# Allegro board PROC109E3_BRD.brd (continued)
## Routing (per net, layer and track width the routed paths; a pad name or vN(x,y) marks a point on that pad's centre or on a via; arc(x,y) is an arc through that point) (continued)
GPIO1_35: length 84.7
  TOP w0.102: U18.M4 81.93,27.36 v2(81.91,27.38)
  L03_SIG1 w0.121: v1(113.59,19.23) 113.15,19.23 112.85,18.93 97.82,18.93 96.62,17.73 84.38,17.73 81.91,20.19 v2(81.91,27.38)
  BOTTOM w0.135: v1(113.59,19.23) 112.9,19.91 112.9,22.73 114.01,23.84 114.01,37.81 111.1,40.71 111.1,52.4 108.05,55.45 108.05,57.92 J6.4
GPIO1_36: length 73
  TOP w0.102: v2(83.94,26.82) 83.98,26.86 U18.T3
  L03_SIG1 w0.121: v1(113.56,21.62) 99.99,21.62 97.43,24.18 85.14,24.18 83.94,25.38 v2(83.94,26.82)
  BOTTOM w0.135: J6.8 110.59,57.91 110.59,55.02 111.49,54.12 111.49,41.03 114.27,38.25 114.27,22.33 v1(113.56,21.62)
GPIO1_40: length 117.7
  TOP w0.102: v2(78.36,27.9) 78.36,27.89 U18.E4
  L03_SIG1 w0.121: v2(78.36,27.9) 77.76,27.9 74.3,24.44 73.47,24.44 71.7,26.22 69.52,26.22 66.22,29.53 66.22,30.41 63.64,32.99 56.07,32.99 54.61,34.44 v1(54.61,35.43)
  BOTTOM w0.135: J6.16 119.24,61.97 86.4,61.97 84.42,59.99 84.42,59.15 82.82,57.55 66.44,57.55 62.84,53.95 62.84,48.23 60.49,45.88 60.49,41.31 v1(54.61,35.43)
GPIO1_41: length 123.3
  TOP w0.102: 77.77,25.02 78.11,25.35 78.11,26.07 U18.D2
  TOP w0.135: v1(130.28,10.08) 100.81,10.08 98.37,12.53 86.15,12.53 82.83,15.85 78.52,15.85 77.87,15.21 76.13,15.21 75.37,15.97 75.37,22.92 76.47,24.02 76.78,24.02 76.78,24.03 77.77,25.02
  BOTTOM w0.135: J6.18 125.84,57.91 128.58,57.91 130.87,55.62 130.87,19.37 130.28,18.77 v1(130.28,10.08)
GPIO1_61: length 2.6
  TOP w0.135: TP34.1 158.72,23.27 U22.7
GPIO1_77: length 98.5
  TOP w0.102: 76.05,33.73 76.33,33.73 76.48,33.58 77.11,33.58 U18.B17
  TOP w0.135: v1(68.35,36.09) 68.38,36.12 70.33,36.12 71.98,34.47 72.8,34.47 73.53,33.73 76.05,33.73
  BOTTOM w0.135: J6.13 118.21,57.92 118.21,59.84 116.35,61.7 86.51,61.7 84.69,59.88 84.69,59.04 82.93,57.28 82.71,57.28 66.55,57.28 63.11,53.84 63.11,50.48 68.16,45.43 71.41,45.43 72.14,44.7 72.14,43.18 69.62,40.66 69.62,40.15 68.35,38.89 v1(68.35,36.09)
GPIO1_78: length 107.7
  TOP w0.102: U18.C16 77.89,32.93 v2(77.86,32.9)
  TOP w0.135: v1(61.89,36.12) 61.89,37.72 62.51,38.34 62.51,43.28 63.33,44.1 66.66,44.1 67.61,45.05 67.61,57.81 69.62,59.82 75.11,59.82 76.91,58.01 81.81,58.01 85.34,61.54 119.39,61.54 120.78,60.15 120.78,57.89 J6.15
  L03_SIG1 w0.121: v1(61.89,36.12) 62.37,36.12 64.75,33.73 66.52,33.73 67.44,32.81 67.44,30.96 67.94,30.45 69.75,30.45 71.15,31.85 76.35,31.85 77.15,32.65 77.6,32.65 v2(77.86,32.9)
GPIO_OSPI0_RESET_N: length 36
  TOP w0.102: 83.06,36.7 83.06,36.63 82.69,36.26 82.69,35.66 U18.M20
  TOP w0.135: v1(83.08,53.14) 83.53,53.14 85.29,51.38 85.29,45.01 83.06,42.78 83.06,36.7
  BOTTOM w0.135: v1(83.08,53.14) 83.79,53.85 83.79,55.55 83.16,56.18 76.25,56.18 75.9,55.83 75.9,53.76 75.75,53.61 75.2,53.61 ; R181.1 75.2,53.61 ; 75.2,53.61 75.2,53.22 75.74,52.69 U31.1
GPIO_RGMII1_PHY_RSTN: length 100.4
  TOP w0.102: U18.Y19 86.67,34.58 87.16,34.58 87.74,35.16 87.74,35.18
  TOP w0.135: v1(96.04,38.58) 94.08,38.58 92.79,37.29 89.84,37.29 87.74,35.18
  L03_SIG1 w0.121: v1(96.04,38.58) 98.78,38.58 99.19,38.99 101.85,38.99 102.2,38.65 110.73,38.65 v1(113.45,41.37)
  BOTTOM w0.135: 142.58,18.86 142.58,18.45 142.44,18.31 U43.1 ; 142.58,18.86 141.92,18.86 140.79,19.99 138.66,19.99 137.62,21.03 135.48,21.03 133.45,19 133.45,9.75 132.74,9.04 129.24,9.04 128.85,9.42 128.85,18.95 127.36,20.45 119.74,20.45 115.39,24.79 115.39,38.28 113.45,40.22 v1(113.45,41.37) ; 142.58,18.86 R275.1
GPIO_RGMII2_PHY_RSTN: length 62.8
  TOP w0.102: 87.74,32.81 87.68,32.86 U18.Y15
  TOP w0.135: 87.74,32.81 94.48,32.81 97.52,35.84 101.88,35.84 102.49,36.45 104.85,36.45 106.79,38.38 108.46,38.38 108.68,38.61 123.29,38.61 v1(124.54,37.36)
  L03_SIG1 w0.121: v1(140.97,39.12) 140.66,38.8 139.35,38.8 138.87,39.28 138.19,39.28 137.92,39.01 125.15,39.01 124.54,38.4 v1(124.54,37.36)
  BOTTOM w0.135: 142.03,37.91 141.29,38.66 141.29,38.8 v1(140.97,39.12) ; 142.03,37.91 R236.1 ; 142.03,37.91 141.73,37.62 141.17,37.62 140.92,37.87 U34.1
LED1: length 45.5
  TOP w0.135: LD15.1 v1(176.75,10.12)
  L03_SIG1 w0.121: v1(176.75,10.12) 175.72,9.09 171.7,9.09 167.67,13.13 167.67,13.89 166.42,15.14 165.12,15.14 159.73,20.52 159.73,21.92 158.37,23.29 158.37,38.94 v1(159.44,40.01)
  BOTTOM w0.135: U35.3 v1(159.44,40.01)
LED2: length 42.2
  TOP w0.135: LD14.1 v1(175.23,10.12)
  L03_SIG1 w0.121: v1(175.23,10.12) 174.5,9.4 171.96,9.4 170.33,11.02 170.33,12.27 167.21,15.39 165.23,15.39 160.02,20.6 160.02,22 158.62,23.39 158.62,37.92 v1(159.44,38.73)
  BOTTOM w0.135: U35.4 v1(159.44,38.73)
LED3: length 38.9
  TOP w0.135: LD13.1 v1(173.73,10.12)
  L03_SIG1 w0.121: v1(159.44,37.47) 158.88,36.91 158.88,26.24 160.32,24.79 160.32,20.66 165.33,15.65 167.36,15.65 170.81,12.19 170.81,10.92 172.08,9.65 173.26,9.65 v1(173.73,10.12)
  BOTTOM w0.135: U35.5 v1(159.44,37.47)
LED4: length 35.1
  TOP w0.135: LD12.1 v1(172.23,10.12)
  L03_SIG1 w0.121: v1(159.44,36.2) 159.16,35.92 159.16,26.82 160.59,25.39 160.59,20.75 165.43,15.91 167.48,15.91 172.23,11.16 v1(172.23,10.12)
  BOTTOM w0.135: v1(159.44,36.2) U35.6
LED_DRV_A0: length 2.6
  BOTTOM w0.135: U35.9 151.03,33.66 150.93,33.55 R245.2
LED_DRV_A1: length 2.6
  BOTTOM w0.135: R241.2 150.77,35.08 150.93,34.93 U35.10
LED_DRV_A2: length 2.9
  BOTTOM w0.135: R243.2 159.66,34.7 159.44,34.93 U35.7
LMK_1G: length 1.9
  TOP w0.135: U6.2 R32.1
LMK_CLK_IN: length 2.6
  TOP w0.135: R26.2 116.93,49.77 117.21,49.49 U6.1
LMK_CLK_IN_R: length 1.8
  TOP w0.135: U3.3 R26.1
MAIN_UART0_RXD: length 63.3
  TOP w0.102: 76.05,29.94 76.16,29.94 76.23,30 76.25,30 76.61,30.36 U18.B10
  TOP w0.135: 76.05,29.94 73.38,29.94 73.21,29.77 71.83,29.77 71.62,29.98 69.75,29.98 68.66,28.88 67.26,28.88 65.58,30.56 63.53,30.56 62.65,29.69 v1(62.65,29.05)
  L03_SIG1 w0.127: v1(62.65,29.05) 63.22,28.49 63.22,21.13 60.6,18.52 40.89,18.52 34.39,12.01 32.51,12.01 32.05,12.47 v1(32.05,13.08)
  BOTTOM w0.135: U45.6 32.98,13.48 32.59,13.08 v1(32.05,13.08)
MAIN_UART0_TXD: length 61.5
  TOP w0.102: U18.B11 77.1,30.56 76.46,30.56 76.32,30.42 76.32,30.36 76.16,30.21 76.05,30.21
  TOP w0.135: 76.05,30.21 73.26,30.21 73.14,30.08 71.9,30.08 71.73,30.25 69.62,30.25 69.16,29.79 66.8,29.79 65.56,31.04 63.45,31.04 62.2,29.79 62.2,28.45 v1(62.57,28.09)
  L03_SIG1 w0.121: 60.55,19.91 40.97,19.91 35,13.94 34.06,13.94 v1(33.15,13.03)
  L03_SIG1 w0.127: v1(62.57,28.09) 61.87,27.4 61.87,21.23 60.55,19.91
  BOTTOM w0.135: v1(33.15,13.03) 33.15,12.56 R592.1 33.9,12.7 33.9,13.18 34.28,13.56 U45.4
MAIN_UART1_CTS#: length 69.8
  TOP w0.102: v2(77.86,31.32) 77.89,31.28 U18.C11
  TOP w0.135: U12.11 98.65,41.02 98.02,40.39 98.02,38.71 96.77,37.47 94.01,37.47 v1(93.29,36.75)
  L03_SIG1 w0.102: v2(77.86,31.32) 77.28,30.73 77.06,30.73
  L03_SIG1 w0.127: 77.06,30.73 75.15,28.82 68.61,28.82 v1(68.1,29.34)
  BOTTOM w0.135: v1(93.29,36.75) 93.29,34.52 94.03,33.78 94.03,24.29 90.35,20.61 75.25,20.61 72.33,23.53 68.82,23.53 68.32,24.02 68.32,24.81 67.78,25.36 67.78,29.02 v1(68.1,29.34)
MAIN_UART1_RTS#: length 108
  TOP w0.114: U18.A11 76.44,30.86 76.32,30.74
  TOP w0.135: U12.5 108.89,41.67 v1(108.9,41.68) ; v1(97.46,10.65) 96.41,10.65 95.61,11.45 85.71,11.45 82.38,14.78 78.96,14.78 78.01,13.83 67.33,13.83 66.57,14.58 66.57,18.21 66.78,18.42 66.78,21.99 66,22.78 66,23.46 65.46,24 65,24 63.22,25.78 63.22,26.7 61.94,27.98 61.94,29.91 63.34,31.31 65.85,31.31 67.09,30.06 69.03,30.06 69.48,30.52 71.9,30.52 72.07,30.35 73.02,30.35 73.15,30.48 76.06,30.48 76.32,30.74
  BOTTOM w0.135: v1(108.9,41.68) 105.08,41.68 97.66,34.26 97.66,14.86 97.67,14.86 97.67,14.6 98.6,13.67 98.6,11.16 98.1,10.65 v1(97.46,10.65)
MAIN_UART1_RXD: length 103.7
  TOP w0.102: U18.B12 77.11,31.64 76.46,31.64 76.05,31.23
  TOP w0.135: 76.05,31.23 75.83,31.01 74.04,31.01 73.39,31.66 71.59,31.66 71.04,31.11 69.32,31.11 69.09,30.89 68.81,30.6 67.65,30.6 66.4,31.85 62.99,31.85 61.4,30.26 61.4,27.52 61.99,26.93 61.99,25.77 66.24,21.51 66.24,18.69 66.03,18.48 66.03,14.31 67.07,13.27 78.22,13.27 79.19,14.24 82.16,14.24 85.74,10.65 v1(95.38,10.65) ; U12.8 v1(100.44,42.97)
  BOTTOM w0.135: v1(100.44,42.97) 100.44,42.38 96.39,38.33 96.39,16.61 95.38,15.6 v1(95.38,10.65)
MAIN_UART1_TXD: length 108.7
  TOP w0.102: 76.05,30.85 76.27,31.07 76.6,31.07 U18.A12
  TOP w0.135: 76.05,30.85 75.95,30.75 73.04,30.75 72.91,30.62 72.23,30.62 72.06,30.78 69.37,30.78 68.92,30.33 67.3,30.33 66.06,31.58 63.1,31.58 61.67,30.14 61.67,27.74 62.26,27.15 62.26,25.88 66.51,21.63 66.51,18.53 66.3,18.32 66.3,14.42 67.18,13.54 78.1,13.54 79.07,14.51 82.27,14.51 85.6,11.18 95.5,11.18 96.46,10.22 98.67,10.22 v1(99.11,10.67) ; U12.2 108.83,39.72 108.84,39.73 v1(108.9,39.73)
  BOTTOM w0.135: v1(108.9,39.73) 103.76,39.73 97.93,33.9 97.93,14.97 99.11,13.79 v1(99.11,10.67)
MAIN_UART2_RXD: length 131.2
  L03_SIG1 w0.121: J1.5 48.77,10.52 65.15,10.52 66.22,9.44 68.85,9.44 73.64,14.23 85.56,14.23 90.77,9.02 128.71,9.02 v1(129.29,9.6)
  BOTTOM w0.135: U32.16 125.66,46.57 125.95,46.29 125.95,45 126.64,44.3 128.65,44.3 130.05,42.9 130.05,24.33 128.83,23.11 128.83,19.35 129.29,18.9 v1(129.29,9.6)
MAIN_UART2_TXD: length 105.3
  TOP w0.102: 84.48,36.7 84.48,36.49 84.19,36.2 84.19,35.66 U18.R20
  TOP w0.135: 84.48,36.7 84.48,37.01 85.05,37.58 85.05,39.23 88.52,42.7 v1(88.52,43.87) 88.52,44.84 R56.1
  L03_SIG1 w0.121: v1(38.3,46.86) 43.15,46.86 43.38,46.63 55.28,46.63 55.8,46.11 64.72,46.11 68.95,50.34 72.21,50.34 72.85,49.7 82.39,49.7 84.1,47.98 84.1,47.04 85.74,45.4 87.95,45.4 88.52,44.83 v1(88.52,43.87)
  BOTTOM w0.135: v1(38.3,46.86) 38.86,46.3 38.86,42.09 40.49,40.46 40.88,40.46 41.43,39.91 41.43,25.12 47.09,19.46 47.09,14.74 J1.7
MAIN_UART4_RXD: length 36.8
  TOP w0.102: U18.L1 81.89,25.02
  TOP w0.135: 81.89,25.02 81.89,20.72 86.81,15.81 86.81,15.68 88.87,13.61 98.96,13.61 100.46,12.12 107.98,12.12 J5.5
MAIN_UART4_TXD: length 49.4
  TOP w0.102: 78.9,25.02 78.9,25.47 79.17,25.75 79.17,26.08 U18.E2
  TOP w0.135: 78.9,25.02 78.9,25 77.11,23.21 76.8,23.21 76.47,22.87 76.47,16.57 77.04,16 77.86,16 v1(78.45,16.59)
  L03_SIG1 w0.127: J5.7 110.65,12.24 100.56,12.24 99.36,13.44 89.97,13.44 87.32,16.08 78.96,16.08 v1(78.45,16.59)
MCAN0_H: length 9.4
  BOTTOM w0.104: J11.1 163.3,10.77 164.16,11.63 165.4,11.63 165.61,11.84 165.61,13.22 164.67,14.16 164.67,14.72 164.57,14.82 164.45,14.82 164.35,14.93 R278.1 164.71,15.83 164.71,16.52 164.52,16.71 U44.7
MCAN0_L: length 9.3
  BOTTOM w0.104: J11.3 167.19,11.63 166.09,11.63 165.89,11.84 165.89,13.34 164.95,14.27 164.95,14.72 165.05,14.82 165.17,14.82 165.27,14.93 R277.2 164.98,15.76 164.98,16.52 165.17,16.71 U44.6
MCAN0_RX: length 9.7
  BOTTOM w0.135: R263.2 160.87,23.56 161.34,24.03 165.94,24.03 166.6,23.37 166.6,21.67 165.82,20.89 U44.4
MCAN0_RX_MUX: length 114
  TOP w0.102: 76.05,32.49 76.07,32.47 76.3,32.47 76.4,32.36 U18.A14
  TOP w0.135: U22.6 v1(156.37,22.77) ; 76.05,32.49 71.22,32.49 70.79,32.05 68.56,32.05 68.28,32.33 v1(68.25,32.33)
  L03_SIG1 w0.121: v1(92.46,22) 92.88,22.42 97.6,22.42 100.2,19.82 112.1,19.82 112.52,20.24 131.52,20.24 132.64,19.13 138.68,19.13 139.39,18.42 149.82,18.42 153.26,21.87 155.47,21.87 v1(156.37,22.77)
  BOTTOM w0.135: v1(92.46,22) 90.8,20.34 75.01,20.34 72.09,23.26 68.43,23.26 67.42,24.27 67.42,31.51 v1(68.25,32.33)
MCAN0_RX_SYNC3_OUT: length 3.7
  TOP w0.135: v1(159.89,22.78) 159.89,22.79 R131.1 159.64,23.77 U22.8
  BOTTOM w0.135: R131.1 159.89,23.52 v1(159.89,22.78)
MCAN0_STB: length 104.1
  TOP w0.102: v2(78.44,26.82) 78.48,26.86 U18.E3
  L03_SIG1 w0.121: v2(78.44,26.82) 78.03,26.41 78.03,24 76.69,22.67 76.69,19.76 79.21,17.24 80.86,17.24 81.39,16.71 100.76,16.71 101.57,17.53 138.43,17.53 140.16,15.8 140.16,14.26 142.37,12.05 157.08,12.05 v1(158.17,13.13)
  BOTTOM w0.135: U44.8 163.87,16.66 163.77,16.56 R276.2 162.11,14.36 160.88,13.13 v1(158.17,13.13)
MCAN0_T: length 6.1
  L03_SIG1 w0.121: v1(163.37,14.5) v1(166.25,14.5)
  BOTTOM w0.135: R277.1 v1(166.25,14.5) 166.51,14.25 167.1,14.25 C267.1 ; R278.2 v1(163.37,14.5)
MCAN0_TX: length 3.7
  BOTTOM w0.135: R259.2 163.52,21.16 163.87,20.81 U44.1
MCAN0_TX_EQEP2_I: length 148.9
  TOP w0.102: 76.05,31.86 U18.B13
  TOP w0.135: v1(69.67,12.52) 69.22,12.98 66.98,12.98 65.76,14.2 65.76,18.49 65.13,19.13 65.13,22.25 61.72,25.66 61.72,26.82 61.13,27.41 61.13,30.37 62.88,32.12 66.51,32.12 67.76,30.87 68.66,30.87 69.19,31.41 70.93,31.41 71.46,31.93 75.93,31.93 75.94,31.93 75.95,31.93 76.01,31.86 76.05,31.86 ; U22.4 154.88,23.27 156.08,22.07 v1(158.55,22.07)
  L03_SIG1 w0.121: v1(69.67,12.52) 72.15,15 86.75,15 89.34,12.41 98.59,12.41 99.9,11.1 138.4,11.1 139.25,10.26 145.08,10.26 146.3,11.48 157.28,11.48 158.88,13.08 158.88,21.74 v1(158.55,22.07)
MCAN0_TX_SYNC2_OUT: length 13.4
  TOP w0.135: U22.2 151.6,24.27 v1(151.31,23.98) 150.96,23.63 R140.1
  BOTTOM w0.135: R259.1 158.8,21.16 155.66,24.29 151.62,24.29 v1(151.31,23.98)
MCAN/EQEP_MUX_SEL: length 99.2
  TOP w0.102: v2(78.92,27.9) 78.92,27.86 79.39,27.39 U18.F4
  TOP w0.135: v1(150.22,25.5) 150.55,25.5 150.75,25.3 150.75,24.99 R128.2 U22.1
  L03_SIG1 w0.121: v2(78.92,27.9) 78.56,28.27 78.2,28.27 78.1,28.17 77.67,28.17 74.42,24.92 v1(73.69,24.92) ; v1(150.22,25.5) 150.22,24.59 148.59,22.96 140.89,22.96 139.8,24.05 139.3,24.05 139,23.76 139,20.96 137.85,19.81 132.92,19.81 131.88,20.85 112.14,20.85 111.62,20.33 100.56,20.33 97.54,23.34 92.58,23.34 92.02,22.78 v1(90.7,22.78)
  BOTTOM w0.135: v1(73.69,24.92) 73.69,23.32 76.05,20.95 89.99,20.95 90.7,21.67 v1(90.7,22.78)
MCU_PORZ: length 69.6
  TOP w0.102: U18.C20 77.89,35.47 78.17,35.75 78.17,35.98 77.45,36.7 77.42,36.7
  TOP w0.135: U1.4 31.56,57.29 31.72,57.12 TP1.1 32.46,55.65 33.11,56.3 34.56,56.3 v1(34.87,56.62) ; v1(74.12,42.18) 74.44,41.86 74.44,39.91 75.11,39.24 75.41,39.24 76.28,38.38 76.28,37.85 77.42,36.7
  L03_SIG1 w0.121: v1(74.12,42.18) 74.12,43.43 72.52,45.03 56.47,45.03 55.15,46.35 43.18,46.35 42.95,46.58 39.65,46.58 39.32,46.25 38.23,46.25 37.59,46.89 35.76,46.89 35.18,46.3 34.21,46.3 33.08,47.44 33.08,50.83 35.26,53.01 35.26,56.24 v1(34.87,56.62)
MCU_RESETSTATZ: length 91.9
  TOP w0.102: U18.A6 76.6,28.07 76.27,28.07 76.05,27.85
  TOP w0.135: v1(72.31,19.03) 71.86,19.48 71.86,20.37 73.1,21.62 73.1,24.49 72.71,24.88 R126.2 74.24,25.4 TP31.1 74.27,26.06 75.31,27.1 75.31,27.1 76.05,27.85
  L03_SIG1 w0.121: v1(62.74,55.09) 63.87,55.09 65.24,56.46 75.47,56.46 v1(76.56,55.38)
  BOTTOM w0.135: v1(62.74,55.09) 59.61,51.97 59.61,43.59 54.5,38.47 54.5,37.12 49.12,31.75 49.12,29.21 48.21,28.29 48.21,24.11 51.41,20.9 63.17,20.9 64.03,20.05 65.19,20.05 66.21,19.03 v1(72.31,19.03) ; R180.1 v1(76.56,55.38)
MCU_RESETZ: length 30.1
  TOP w0.102: U18.A5 76.45,27.86 76.05,27.47
  TOP w0.135: U13.7 59.26,40.43 60.12,39.57 TP19.1 61.44,39.52 61.44,34.14 v1(61.93,33.66) ; 76.05,27.47 75.58,26.99 75.58,26.71 v1(74.78,25.91)
  L03_SIG1 w0.121: v1(61.93,33.66) 63.42,33.66 66.47,30.61 66.47,29.63 69.63,26.47 72.25,26.47 72.57,26.16 74.53,26.16 v1(74.78,25.91)
MCU_SAFTY_ERRZ: length 5.6
  TOP w0.102: U18.B20 77.11,35.08 76.6,35.08
  TOP w0.135: 76.6,35.08 76.5,35.08 74.62,36.96 TP22.1
MCU_UART0_CTS#: length 67.2
  TOP w0.102: U18.D4 77.86,26.82 77.85,26.82 v2(77.86,26.82)
  TOP w0.135: U8.11 v1(103.1,47.88)
  L03_SIG1 w0.121: v2(77.86,26.82) 77.6,26.56 77.6,24.05 76.44,22.89 76.44,19.63 79.08,16.98 80.72,16.98 81.33,16.38 87.5,16.38 88.47,15.42 v1(96.44,15.42)
  BOTTOM w0.135: v1(103.1,47.88) 103.1,43.72 100.17,40.79 99.64,40.79 96.76,37.91 96.76,15.73 v1(96.44,15.42)
MCU_UART0_RTS#: length 81.2
  TOP w0.102: U18.C2 77.89,25.52 77.89,25.51
  TOP w0.114: 77.89,25.51 77.39,25.02
  TOP w0.135: 77.39,25.02 76.67,24.29 76.36,24.29 75.1,23.03 75.1,15.73 75.89,14.94 77.98,14.94 78.63,15.59 82.71,15.59 86.04,12.26 97.6,12.26 v1(98.12,11.73) ; U8.5 108.89,48.53 v1(108.9,48.54)
  BOTTOM w0.135: v1(108.9,48.54) 109.4,48.04 109.4,45.97 108.46,45.03 107.85,45.03 97.37,34.56 97.37,14.94 97.38,12.48 v1(98.12,11.73)
MCU_UART0_RXD: length 88.9
  TOP w0.102: U18.D6 78.39,28.78 v2(78.44,28.82)
  TOP w0.135: U8.8 100.4,49.83 99.36,48.79 v1(99.36,42.98)
  L03_SIG1 w0.121: v1(66.73,32.56) 66.73,29.74 69.73,26.73 72.46,26.73 72.77,26.41 75.26,26.41 77.29,28.45 78.07,28.45 v2(78.44,28.82)
  BOTTOM w0.135: v1(99.36,42.98) 99.36,41.96 97.42,40.02 96.66,40.02 93.9,37.26 93.9,36.7 93.65,36.45 93.65,34.65 94.54,33.76 94.54,22.4 91.94,19.81 74.59,19.81 71.68,22.72 68.11,22.72 66.88,23.95 66.88,32.4 v1(66.73,32.56)
MCU_UART0_TXD: length 77.5
  TOP w0.102: U18.B2 77.69,26.06 77.69,25.67 77.04,25.02 77.01,25.02
  TOP w0.135: 77.01,25.02 76.56,24.56 76.25,24.56 74.83,23.15 74.83,15.61 75.78,14.67 78.09,14.67 78.74,15.32 82.6,15.32 85.93,11.99 96.52,11.99 v1(96.77,11.73) ; v1(108.9,46.58) 108.84,46.58 108.83,46.58 U8.2
  BOTTOM w0.135: v1(96.77,11.73) 97.1,12.07 97.1,34.79 v1(108.9,46.58)
OBSCLK0: length 107.3
  L03_SIG1 w0.121: v1(135.53,56.82) 133.55,54.84 110.77,54.84 107.34,51.41 89.74,51.41 87.29,53.86 82.52,53.86 81.85,54.52 78.93,54.52 78.57,54.15 71.12,54.15 70.71,53.75 69.36,53.75 68.66,54.46 v1(65.25,54.46)
  BOTTOM w0.135: v1(135.53,56.82) 137.77,56.82 138.79,55.8 R185.1 ; R240.2 71.04,35.23 70.33,35.94 70.33,37.69 70.46,37.82 70.46,40.36 73.18,43.08 73.18,44.81 71.04,46.94 67.82,46.94 63.92,50.84 63.92,53.5 64.87,54.46 v1(65.25,54.46)
OSC0: length 8.6
  BOTTOM w0.135: U37.88 15.78,38.69 15.53,38.43 C131.2 15.09,38.44 14.55,38.99 12.47,38.99 11.5,38.02 Y1.3
OSC0_XO: length 6.7
  TOP w0.102: U18.C21 77.05,36.7 76.73,36.7
  TOP w0.135: 76.73,36.7 74.8,38.63 74.47,38.63 73.72,39.39 R78.2
OSC1: length 6.5
  BOTTOM w0.135: Y1.1 13.92,39.27 C120.2 15.53,39.27 15.71,39.09 U37.89
OSC_STB#: length 1.8
  TOP w0.135: U3.1 R49.2
OSPI0_CLK: length 26.5
  TOP w0.135: U2.16 70.71,46.74 70.38,47.07 69.93,47.07 69.47,46.61 69.47,46.01 R54.1 72.95,45.77 73.66,46.48 73.66,48.07 73.97,48.39 74.36,48.39 74.68,48.07 74.68,46.91 75.15,46.44 75.63,46.44 v1(75.95,46.76) ; R63.2 v1(84.3,42.9)
  BOTTOM w0.135: v1(75.95,46.76) 78.4,44.31 84.88,44.31 85.01,44.17 85.01,43.04 84.88,42.9 v1(84.3,42.9)
OSPI0_CLK_R: length 6.4
  TOP w0.102: 83.6,36.7 83.6,36.52 83.11,36.03 83.11,35.64 U18.P20
  TOP w0.135: 83.6,36.7 83.6,39.89 84.3,40.59 R63.1
OSPI0_CS0_N: length 32.8
  TOP w0.102: U18.L20 81.61,35.64 81.61,36.22
  TOP w0.135: v1(83.14,54.35) 83.14,54.36 U2.7 ; v1(77.39,48.23) 77.39,49.17 77.26,49.3 75.9,49.3 75.77,49.17 75.77,48.03 76.48,47.32 78.03,47.32 82.02,43.33 82.02,39.67 81.63,39.29 81.63,36.24 81.61,36.22
  BOTTOM w0.135: v1(77.39,48.23) 76.86,48.77 76.86,49.83 77.72,50.7 79.63,50.7 81.69,52.76 R183.1 82.01,54.35 v1(83.14,54.35)
OSPI0_D0: length 35.2
  TOP w0.102: v2(82.44,34.89) 82.41,34.86 U18.L19
  TOP w0.135: v1(70.56,49.35) 70.01,48.8 R36.1 70.47,48.01 U2.15
  L03_SIG1 w0.121: v2(82.44,34.89) 83.02,35.47 83.02,39.33 82.69,39.67 82.69,45.97 80.08,48.57 78.54,48.57 78.23,48.26 78.23,46.94 77.19,45.9 74.22,45.9 73.55,46.57 73.55,46.84 73.75,47.04 73.75,47.21 73.58,47.38 73.41,47.38 73.06,47.03 72.89,47.03 72.72,47.2 72.72,47.37 73.06,47.72 73.06,47.89 72.89,48.06 72.72,48.06 72.37,47.71 72.2,47.71 72.03,47.88 72.03,48.05 72.38,48.4 72.38,48.57 72.21,48.74 72.04,48.74 71.69,48.39 71.52,48.39 v1(70.56,49.35)
OSPI0_D1: length 35.7
  TOP w0.102: 83.33,36.7 83.33,36.62 82.89,36.18 U18.N20
  TOP w0.135: U2.8 R10.1 84.63,55.63 84.95,55.31 86.24,55.31 86.41,55.14 86.41,54.81 86.25,54.65 83.88,54.65 83.74,54.51 83.74,54.19 83.88,54.06 86.73,54.06 86.87,53.92 86.87,53.63 86.73,53.49 84.16,53.49 84.02,53.36 84.02,53.06 84.16,52.93 85.44,52.93 85.57,52.8 85.57,44.88 83.33,42.64 83.33,36.7
OSPI0_D2: length 35.7
  TOP w0.102: U18.L21 81.89,36.7 81.9,36.7
  TOP w0.135: U2.9 72.04,57.09 R5.1 73.29,57.22 74.61,55.9 74.61,54.14 73.79,53.32 73.79,53.13 73.98,52.94 74.17,52.94 74.99,53.76 75.18,53.76 75.37,53.57 75.37,53.38 74.55,52.56 74.55,52.37 74.74,52.18 74.93,52.18 75.75,53 75.94,53 76.13,52.81 76.13,52.62 75.31,51.8 75.31,51.61 75.5,51.42 75.69,51.42 76.51,52.24 76.77,52.24 77.98,51.03 77.98,47.75 82.38,43.35 82.38,39.61 81.9,39.13 81.9,36.7
OSPI0_D3: length 35.3
  TOP w0.102: v2(83.37,34.89) 83.33,34.86 U18.N19
  TOP w0.135: v1(83.36,46.74) 83.72,47.09 83.72,47.98 83.54,48.16 R37.1 82.98,48.16 82.8,47.98 82.8,46.87 82.67,46.74 U2.1
  L03_SIG1 w0.121: v1(83.36,46.74) 83.05,47.05 83.05,47.95 81.93,49.07 81.2,49.07 80.72,48.59 80.72,48.36 81.15,47.93 81.42,47.93 81.82,48.34 82.02,48.34 82.31,48.04 82.31,47.87 81.85,47.4 81.85,47.23 83.21,45.87 84.18,45.87 84.3,45.75 84.3,45.23 84.18,45.11 83.82,45.11 83.62,44.91 83.62,44.5 83.74,44.38 85.27,44.38 85.39,44.26 85.39,44.02 85.27,43.9 83.74,43.9 83.62,43.78 83.62,43.54 83.74,43.42 85.05,43.42 85.17,43.3 85.17,42.57 84.94,42.34 83.06,42.34 82.94,42.22 82.94,41.73 83.06,41.6 83.67,41.6 83.79,41.48 83.79,41.17 83.29,40.67 83.29,34.98 v2(83.37,34.89)
OSPI0_DQS: length 45.9
  TOP w0.102: v2(83.94,34.33) 83.45,33.86 U18.P17
  L03_SIG1 w0.121: v1(95.81,41.37) 98.56,41.37 98.73,41.2 98.73,40.33 98.56,40.16 93.94,40.16 93.82,40.28 93.82,41.18 93.7,41.3 93.46,41.3 93.34,41.18 93.34,40.28 93.22,40.16 92.98,40.16 92.85,40.28 92.85,41.18 92.73,41.3 92.49,41.3 92.37,41.18 92.37,40.28 92.25,40.16 92.01,40.16 91.89,40.28 91.89,41.18 91.77,41.3 91.53,41.3 91.41,41.18 91.41,40.28 91.29,40.16 91.04,40.16 90.92,40.28 90.92,41.18 90.8,41.3 90.56,41.3 90.44,41.18 90.44,40.28 90.32,40.16 90.08,40.16 89.96,40.28 89.96,41.18 89.84,41.3 89.22,41.3 88.29,42.23 87.77,42.23 87.53,41.99 87.53,39.24 87.38,39.09 86.64,39.09 86.44,39.29 86.44,42.06 86.18,42.32 85.65,42.32 83.88,40.54 83.88,36.31 84.3,35.89 84.3,34.69 v2(83.94,34.33)
  BOTTOM w0.135: R213.1 95.78,44.85 95.38,44.45 95.38,41.81 v1(95.81,41.37)
OSPI0_DQS_R: length 16.7
  TOP w0.135: v1(84.81,47.35) 84.81,46.33 83.8,45.32 R65.1
  L03_SIG1 w0.121: v1(96.55,45.82) 96.12,45.4 91.71,45.4 90.75,46.36 90.12,46.36 89.84,46.08 86.63,46.08 85.37,47.35 v1(84.81,47.35)
  BOTTOM w0.135: R213.2 96.52,45.83 96.52,45.82 v1(96.55,45.82)
OSPI0_LBCLKO: length 9
  TOP w0.102: 82.17,36.7 82.17,36.09 U18.M21
  TOP w0.135: R65.2 82.65,43.78 82.65,39.5 82.17,39.01 82.17,38.96 82.17,38.96 82.17,36.7
PORZ_OUT: length 224.9
  TOP w0.102: v2(77.86,34.89) U18.D18 ; v2(77.86,34.89) 77.86,34.9 77.86,34.9 v2(77.86,34.89)
  TOP w0.135: v1(78.94,52.85) 78.94,56.21 80.09,57.35 82.12,57.35 85.76,61 117,61 118.24,59.77 v1(118.24,55.37) 118.9,54.71 121.79,54.71 123.09,53.41 123.09,50.67 123.65,50.11 123.65,47.14 125.53,45.26 129.46,45.26 130.73,43.99 130.73,41.5 132.49,39.75 139.32,39.75 v1(139.7,39.37) 139.7,38.05 138.61,36.96 135.03,36.96 130.96,32.89 130.96,22.73 133.68,20.02 139.27,20.02 v1(139.95,19.33) ; R87.2 72.61,39.29 72.42,39.48 TP14.1 72.24,40.18 v1(72.24,40.85)
  L03_SIG1 w0.121: v1(72.24,40.85) 71.2,40.85 70.11,39.76 70.11,36.39 71.2,35.31 77.45,35.31 v2(77.86,34.89) ; v1(78.94,52.85) 78.11,52.02 76.05,52.02 75.46,52.61 67.86,52.61 67.47,53 64.53,53 64.05,52.53 40.26,52.53 v1(39.17,51.44)
  BOTTOM w0.135: U34.2 139.4,38.62 139.7,38.92 v1(139.7,39.37) ; U43.2 v1(139.95,19.33) ; U32.8 117.92,51.12 117.53,51.52 117.53,54.66 v1(118.24,55.37) ; v1(72.24,40.85) 73.21,40.85 73.48,41.12 73.48,44.88 71.15,47.22 67.92,47.22 64.19,50.95 64.19,53.09 64.85,53.75 65.23,53.75 65.79,54.31 65.79,55.17 66.32,55.7 67.87,55.7 72.6,50.97 78.15,50.97 78.94,51.77 v1(78.94,52.85) 78.94,54.19 78.55,54.59 R179.1 ; U28.2 v1(39.17,51.44)
PRG1_CPSW_ETH1_CLK_OUT: length 2.6
  TOP w0.135: U19.40 138.68,23.09 TP33.1
PRG1_CPSW_ETH1_D0M: length 31.5
  TOP w0.102: J19.10 170.26,31.11 169.81,31.56 168.43,31.56 166.53,29.66 166.53,28.29 164.92,26.68 144.18,26.68 144.08,26.78 U19.2
PRG1_CPSW_ETH1_D0P: length 31.5
  TOP w0.102: J19.9 169.85,29.84 170.29,30.28 170.29,30.66 169.69,31.27 168.55,31.27 166.83,29.54 166.83,28.17 165.04,26.38 144.18,26.38 144.08,26.28 U19.1
PRG1_CPSW_ETH1_D1M: length 30.2
  TOP w0.102: v1(164.13,28.49) 163.83,28.18 144.18,28.18 144.08,28.28 U19.5
  BOTTOM w0.102: J19.8 171.64,28.34 170.6,28.34 170.24,28.7 167.89,28.7 167.23,28.04 163.89,28.04 163.78,28.15 163.78,28.39 163.87,28.49 v1(164.13,28.49)
PRG1_CPSW_ETH1_D1P: length 30.1
  TOP w0.102: v1(164.13,27.58) 163.83,27.88 144.18,27.88 144.08,27.78 U19.4
  BOTTOM w0.102: J19.7 169.75,26.87 170.31,26.87 170.52,27.08 170.52,28 170.12,28.4 168.01,28.4 167.36,27.74 164.3,27.74 v1(164.13,27.58)
PRG1_CPSW_ETH1_D2M: length 41.5
  TOP w0.102: U19.8 144.08,29.78 144.18,29.68 164.59,29.68 168.06,33.15 172.14,33.15 173.26,32.03 173.26,27.66 172.78,27.18 171.27,27.18 170.64,26.55 170.64,25.75 170.82,25.58 171.41,25.58 J19.6
PRG1_CPSW_ETH1_D2P: length 41.5
  TOP w0.102: U19.7 144.08,29.28 144.18,29.38 164.71,29.38 168.18,32.85 172.02,32.85 172.96,31.91 172.96,27.78 172.66,27.48 171.15,27.48 170.35,26.67 170.35,24.86 170.25,24.76 J19.5
PRG1_CPSW_ETH1_D3M: length 44.3
  TOP w0.102: v1(163.88,31.49) 163.57,31.18 144.18,31.18 144.08,31.28 U19.11
  BOTTOM w0.102: v1(163.88,31.49) 163.65,31.49 163.53,31.37 163.53,31.14 163.64,31.03 166.85,31.03 168.36,32.53 172.73,32.53 173.71,31.55 173.71,25.4 172.95,24.64 171.36,24.64 170.76,24.05 170.76,23.32 171.02,23.06 171.44,23.06 J19.4
PRG1_CPSW_ETH1_D3P: length 44.3
  TOP w0.102: U19.10 144.08,30.78 144.18,30.88 163.57,30.88 v1(163.88,30.57)
  BOTTOM w0.102: v1(163.88,30.57) 164.04,30.73 166.98,30.73 168.48,32.23 172.6,32.23 173.41,31.42 173.41,25.52 172.83,24.94 171.23,24.94 170.47,24.17 170.47,21.89 170.29,21.71 169.83,21.71 J19.3
PRG1_CPSW_ETH1_LED1: length 26.2
  BOTTOM w0.135: Q13.2 Q13.1 163.59,33.56 Q13.8 164.24,33.56 Q13.6 ; Q13.5 Q13.6 ; Q13.6 172.91,33.56 175.64,36.3 181.95,36.3 182.79,35.46 J19.12
PRG1_CPSW_ETH1_LED2: length 34.9
  L03_SIG1 w0.121: v1(161.47,27.36) 165.23,23.6 165.23,21.31 169.6,16.94 169.6,15.54 170.94,14.2 176.28,14.2 J19.13
  BOTTOM w0.135: Q14.6 160.76,27.36 v1(161.47,27.36) ; Q14.6 160.1,27.34 Q14.8 159.45,27.34 Q14.1 ; Q14.6 Q14.5 ; R252.1 157.92,26.97 158.3,27.34 Q14.1 ; Q14.2 Q14.1
PRG1_CPSW_ETH1_LED3: length 41.2
  L03_SIG1 w0.121: v1(161.47,30.25) 160.91,29.69 160.91,26.7 161.8,25.81 162.61,25.81 164.9,23.52 164.9,21.13 169.11,16.92 169.11,15.65 170.89,13.87 177.98,13.87 J19.14
  BOTTOM w0.135: R257.1 157,30.24 Q15.1 ; Q15.1 159.45,30.24 Q15.8 160.1,30.24 Q15.6 ; Q15.1 Q15.2 ; v1(161.47,30.25) 160.76,30.25 Q15.6 ; Q15.6 Q15.5
PRG1_CPSW_ETH1_LED_1000/RX_ER: length 97.7
  TOP w0.102: U18.U14 84.62,32.09 84.62,32.09 v2(84.38,31.85)
  TOP w0.135: U19.46 141.68,24.84 142.42,24.1 144.61,24.1 144.76,23.95 R138.1 145,23.16 145.32,23.16 v1(145.56,23.4)
  L03_SIG1 w0.121: v1(117.47,35.51) 117.06,35.1 108.76,35.1 105.97,32.31 105.97,31.26 105.56,30.86 99.77,30.86 97.94,32.69 87.35,32.69 86.62,31.96 84.49,31.96 v2(84.38,31.85) ; v1(145.56,23.4) 144.96,24 143.13,24 142.55,24.58 142.55,31.7 140.34,33.91 v1(129.41,33.91)
  BOTTOM w0.135: Q14.3 158.8,29.06 158.52,29.34 152.27,29.34 147.07,24.13 146.29,24.13 v1(145.56,23.4) R138.1 ; v1(129.41,33.91) 129.1,33.59 119.39,33.59 v1(117.47,35.51)
PRG1_CPSW_ETH1_LED_ACT: length 84.9
  TOP w0.135: v1(123.06,34.8) 116.71,34.8 113.71,37.8 109.43,37.8 105.79,34.16 105.16,34.16 104.01,33.02 v1(104.01,32.44) ; v1(144.02,23.39) 143.81,23.19 143.5,23.19 R137.1 143.25,23.4 142.81,23.84 142.21,23.84 141.18,24.86 U19.45
  L03_SIG1 w0.121: v1(123.06,34.8) 123.95,33.91 128.52,33.91 128.95,33.49 137.33,33.49 138.18,32.64 141.1,32.64 142.29,31.44 142.29,24.46 143.36,23.39 v1(144.02,23.39)
  BOTTOM w0.135: R594.2 v1(104.01,32.44) ; R137.1 144.01,23.4 v1(144.02,23.39) 144.02,23.84 144.69,24.51 146.94,24.51 152.03,29.61 158.63,29.61 158.65,29.59 161.54,29.59 162.05,30.1 162.05,34.54 162.37,34.86 Q13.3
PRG1_CPSW_ETH1_LED_LINK: length 82.9
  TOP w0.102: U18.Y13 86.67,31.58 87.01,31.58 87.13,31.7 87.74,31.7
  TOP w0.135: v1(124.46,34.8) 123.06,36.2 115.95,36.2 114.08,38.07 108.9,38.07 108.68,37.85 108.08,37.85 105.87,35.63 103.96,35.63 103,34.67 103,33.76 102.64,33.4 101.93,33.4 101.24,34.09 99.74,34.09 99.44,33.78 97.28,33.78 95.2,31.7 87.74,31.7 ; U19.47 142.18,24.84 142.64,24.38 146.15,24.38 146.59,23.95 R139.1 146.8,23.19 147.18,23.19 v1(147.39,23.4)
  L03_SIG1 w0.121: v1(124.46,34.8) 139.81,34.8 142.94,31.66 142.94,24.66 143.22,24.38 146.41,24.38 v1(147.39,23.4)
  BOTTOM w0.135: R139.1 v1(147.39,23.4)
PRG1_CPSW_ETH1_RBIAS: length 1.3
  TOP w0.254: U19.12 R102.1
PRG1_CPSW_ETH2_CLK_OUT: length 2.6
  TOP w0.135: U7.40 138.68,42.14 TP11.1
PRG1_CPSW_ETH2_D0M: length 34.2
  TOP w0.102: U7.2 144.08,45.83 144.18,45.73 164.87,45.73 167.19,48.05 167.19,52.14 168.46,53.41 169.81,53.41 170.26,52.96 J18.10
PRG1_CPSW_ETH2_D0P: length 34.2
  TOP w0.102: J18.9 169.83,51.69 170.26,52.12 170.26,52.54 169.69,53.12 168.58,53.12 167.49,52.02 167.49,47.93 164.99,45.43 144.18,45.43 144.08,45.33 U7.1
PRG1_CPSW_ETH2_D1M: length 31.3
  TOP w0.102: v1(163.88,47.54) 163.57,47.23 144.18,47.23 144.08,47.33 U7.5
  BOTTOM w0.102: J18.8 171.64,50.19 170.66,50.19 170.3,50.55 168.18,50.55 164.73,47.09 163.63,47.09 163.5,47.22 163.5,47.39 163.65,47.54 v1(163.88,47.54)
PRG1_CPSW_ETH2_D1P: length 31.3
  TOP w0.102: U7.4 144.08,46.83 144.18,46.93 163.57,46.93 v1(163.88,46.63)
  BOTTOM w0.102: J18.7 169.73,48.74 170.34,48.74 170.52,48.92 170.52,49.91 170.18,50.25 168.31,50.25 164.85,46.79 164.05,46.79 v1(163.88,46.63)
PRG1_CPSW_ETH2_D2M: length 44.5
  TOP w0.102: U7.8 144.08,48.83 144.18,48.73 164,48.73 165.67,50.4 165.67,53.21 167.45,55 172.14,55 173.52,53.62 173.52,49.76 172.78,49.03 171.27,49.03 170.64,48.4 170.64,47.6 170.77,47.47 171.46,47.47 J18.6
PRG1_CPSW_ETH2_D2P: length 44.5
  TOP w0.102: U7.7 144.08,48.33 144.18,48.43 164.12,48.43 165.96,50.28 165.96,53.09 167.58,54.7 172.02,54.7 173.22,53.5 173.22,49.89 172.66,49.32 171.15,49.32 170.35,48.52 170.35,46.78 170.18,46.61 J18.5
PRG1_CPSW_ETH2_D3M: length 45.5
  TOP w0.102: v1(163.88,50.54) 163.57,50.23 144.18,50.23 144.08,50.33 U7.11
  BOTTOM w0.102: v1(163.88,50.54) 163.6,50.54 163.5,50.44 163.5,50.2 163.6,50.1 164.74,50.1 169.07,54.43 172.67,54.43 173.71,53.39 173.71,47.25 172.95,46.49 171.36,46.49 170.76,45.9 170.76,45.17 171,44.93 171.46,44.93 J18.4
PRG1_CPSW_ETH2_D3P: length 45.5
  TOP w0.102: v1(163.88,49.62) 163.57,49.93 144.18,49.93 144.08,49.83 U7.10
  BOTTOM w0.102: J18.3 169.83,43.56 170.29,43.56 170.47,43.74 170.47,46.02 171.23,46.78 172.83,46.78 173.41,47.37 173.41,53.27 172.55,54.14 169.2,54.14 164.87,49.81 164.06,49.81 v1(163.88,49.62)
PRG1_CPSW_ETH2_LED1: length 24.4
  BOTTOM w0.135: Q10.2 Q10.1 164.14,53.2 Q10.8 164.79,53.2 Q10.6 Q10.5 166.85,53.85 170.03,57.02 181.44,57.02 182.79,55.68 J18.12
PRG1_CPSW_ETH2_LED2: length 23.1
  L03_SIG1 w0.121: J18.13 176.66,36.42 166.7,36.42 v1(165.68,37.44)
  BOTTOM w0.135: Q11.1 163.59,36.79 Q11.8 164.24,36.79 Q11.6 Q11.5 v1(165.68,37.44) ; Q11.1 Q11.2 ; Q11.1 161.94,36.79 161.93,36.8 R220.1
PRG1_CPSW_ETH2_LED3: length 29.1
  L03_SIG1 w0.121: v1(165.68,40.34) 165.68,38.56 165.23,38.1 165.23,37.21 166.37,36.07 178.34,36.07 J18.14
  BOTTOM w0.135: R223.1 162.93,39.69 Q12.1 ; Q12.1 Q12.2 ; Q12.1 163.59,39.69 Q12.8 164.24,39.69 Q12.6 Q12.5 v1(165.68,40.34)
PRG1_CPSW_ETH2_LED_1000/RX_ER: length 105.9
  TOP w0.102: 87.58,30.63 87.57,30.63 87.12,30.63 U18.AA11
  TOP w0.135: 87.58,30.63 88.57,30.63 89.16,30.04 96.97,30.04 98.73,31.8 v1(98.73,32.56) ; v1(143.99,42.45) 143.77,42.24 143.5,42.24 R75.1 143.29,42.9 143.08,43.1 142.42,43.1 141.68,43.84 U7.46
  L03_SIG1 w0.121: v1(143.99,42.45) 142.75,43.69 142.75,48.77 140.14,51.38 136.6,51.38 135.8,52.18 130.54,52.18 129.7,51.34 124.54,51.34 124.2,51.68 124.05,51.83 121.47,51.83 120.78,51.13 120.78,48.82 114.7,42.75 114.7,42.14 114.35,41.79 113.14,41.79 110.47,39.12 v1(109.6,39.12)
  BOTTOM w0.135: R75.1 v1(143.99,42.45) 144.57,43.04 148.7,43.04 148.72,43.05 149.12,43.05 149.89,43.82 160.02,43.82 160.66,43.18 160.66,39.25 160.92,38.99 162.56,38.99 162.94,38.61 Q11.3 ; v1(98.73,32.56) 98.73,33.45 103.5,38.23 108.71,38.23 v1(109.6,39.12)
PRG1_CPSW_ETH2_LED_ACT: length 92.5
  TOP w0.135: U7.45 141.18,43.75 141.79,43.15 R74.1 142,42.24 142.32,42.24 v1(142.52,42.44) ; R596.2 99.07,37.6 v1(99.06,37.59)
  L03_SIG1 w0.121: v1(99.06,37.59) 100.33,37.59 101.13,38.39 111.31,38.39 114.95,42.04 114.95,42.64 121.41,49.1 121.41,50.5 122.49,51.57 123.94,51.57 124.43,51.08 129.91,51.08 130.75,51.92 135.69,51.92 136.49,51.12 140.03,51.12 142.11,49.04 142.11,42.85 v1(142.52,42.44)
  BOTTOM w0.135: Q10.3 162.2,54.5 161.54,53.84 161.54,49.02 157.86,45.34 150.62,45.34 148.59,43.31 142.93,43.31 142.52,42.89 v1(142.52,42.44) 142.51,42.45 R227.2
PRG1_CPSW_ETH2_LED_LINK: length 80
  TOP w0.102: v2(85.93,30.4) 85.89,30.44 U18.W11
  TOP w0.135: v1(132.08,41.4) 132.08,40.77 132.72,40.13 140.59,40.13 140.97,39.75 146.18,39.75 146.81,40.39 146.81,42.16 146.53,42.44 v1(145.8,42.44) 145.59,42.24 145.22,42.24 R76.1 145.01,43 144.61,43.41 142.57,43.41 142.18,43.8 U7.47
  L03_SIG1 w0.121: v2(85.93,30.4) 87.38,30.4 87.75,30.03 96.11,30.03 97.28,28.85 102.97,28.85 103.6,28.22 104.37,28.22 106.76,30.61 106.76,31.42 109.93,34.59 118.34,34.59 119.76,36.01 119.76,38.35 121.03,39.62 123.82,39.62 125.12,40.92 131.6,40.92 v1(132.08,41.4)
  BOTTOM w0.135: v1(145.8,42.44) 145.79,42.45 R225.2
PRG1_CPSW_ETH2_RBIAS: length 1.3
  TOP w0.254: U7.12 R22.1
PRG1_CPSW_RGMII1_CLK: length 32.7
  TOP w0.135: U19.20 139.18,33.16 v1(138.96,33.38) ; v1(131.75,48.92) 130.3,50.37 R25.2
  BOTTOM w0.135: v1(131.75,48.92) 132.33,48.92 133.25,49.83 134.39,49.83 138.81,45.42 140.34,45.42 141.22,44.53 141.22,42.7 139.77,41.25 139.77,40.18 138.98,39.38 138.92,39.38 138.91,39.37 137.97,39.37 136.96,38.36 136.96,34.03 137.62,33.38 v1(138.96,33.38)
PRG1_CPSW_RGMII1_CLK_R: length 2.7
  TOP w0.135: U6.8 125.69,49.49 125.96,49.76 125.96,50.09 126.24,50.37 R25.1
PRG1_CPSW_RGMII1_GPIO_1: length 26
  TOP w0.135: U19.22 R95.2 137.97,34.54 137.59,34.54 v1(137.39,34.34)
  BOTTOM w0.135: Q15.3 158.8,32.09 158.37,32.51 147.45,32.51 145.92,34.04 142.24,34.04 141.86,33.66 139.7,33.66 139.02,34.33 R95.2 137.4,34.33 v1(137.39,34.34)
PRG1_CPSW_RGMII1_RD0: length 33.9
  TOP w0.135: v1(133.99,26.85) 133.78,26.64 133.78,26.31 R123.1 134.51,26.12 134.67,26.29 134.67,26.95 135.5,27.78 U19.33
  L03_SIG1 w0.121: v1(111.87,27.84) 112.37,27.84 114.65,25.56 126.17,25.56 126.29,25.44 126.29,25.09 126.41,24.97 126.65,24.97 126.77,25.09 126.77,25.44 126.89,25.56 127.13,25.56 127.25,25.44 127.25,25.09 127.37,24.97 127.61,24.97 127.74,25.09 127.74,25.44 127.86,25.56 128.1,25.56 128.22,25.44 128.22,25.09 128.34,24.97 128.58,24.97 128.7,25.09 128.7,25.44 128.82,25.56 132.7,25.56 v1(133.99,26.85)
  BOTTOM w0.135: v1(133.99,26.85) 133.99,26.07 R254.2 ; v1(111.87,27.84) 111.37,28.34 U40.11
PRG1_CPSW_RGMII1_RD1: length 33.8
  TOP w0.135: v1(133.99,25.39) 133.99,25.37 133.76,25.15 133.76,24.9 R129.2 134.52,24.69 134.95,25.12 134.95,26.67 135.56,27.28 U19.34
  L03_SIG1 w0.121: v1(110.68,27.84) 111.19,27.33 112.34,27.33 115.41,24.27 120.35,24.27 120.47,24.39 120.47,24.67 120.59,24.79 120.83,24.79 120.95,24.67 120.95,24.39 121.07,24.27 121.31,24.27 121.43,24.39 121.43,24.67 121.55,24.79 121.8,24.79 121.92,24.67 121.92,24.39 122.04,24.27 132.86,24.27 v1(133.99,25.39)
  BOTTOM w0.135: v1(133.99,25.39) 133.99,24.7 R129.2 ; U40.12 v1(110.68,27.84)
PRG1_CPSW_RGMII1_RD2: length 33.8
  TOP w0.135: v1(132.5,23.39) 133.23,23.39 133.24,23.4 ; 133.24,23.4 133.82,23.98 134.29,23.98 135.25,24.94 135.25,26.55 135.49,26.78 U19.35 ; 133.24,23.4 R132.1
  L03_SIG1 w0.121: v1(111.87,26.84) 112.38,26.84 115.82,23.39 122.79,23.39 122.91,23.51 122.91,23.83 123.03,23.95 123.27,23.95 123.39,23.83 123.39,23.51 123.51,23.39 123.75,23.39 123.88,23.51 123.88,23.83 124,23.95 124.24,23.95 124.36,23.83 124.36,23.51 124.48,23.39 124.72,23.39 124.84,23.51 124.84,23.76 124.96,23.88 125.2,23.88 125.32,23.76 125.32,23.51 125.44,23.39 v1(132.5,23.39)
  BOTTOM w0.135: v1(111.87,26.84) 111.37,27.34 U40.13 ; v1(132.5,23.39) 132.51,23.4 R132.1
PRG1_CPSW_RGMII1_RD3: length 33.8
  TOP w0.135: U19.36 135.74,26.28 135.53,26.07 135.53,24.76 134.73,23.95 R133.1 134.94,23.19 135.28,23.19 v1(135.48,23.39)
  L03_SIG1 w0.121: v1(110.68,26.84) 111.18,26.34 112.34,26.34 115.71,22.97 133.18,22.97 134.26,24.05 134.82,24.05 v1(135.48,23.39)
  BOTTOM w0.135: v1(135.48,23.39) 134.73,23.39 R133.1 ; U40.14 v1(110.68,26.84)
PRG1_CPSW_RGMII1_RSTN: length 5.5
  TOP w0.135: U19.43 140.18,24.54 v1(140.61,24.1)
  BOTTOM w0.135: U43.4 139,21.91 140.61,23.52 v1(140.61,24.1)
PRG1_CPSW_RGMII1_RX_CTL: length 33.8
  TOP w0.135: U19.38 137.68,24.6 137.37,24.28 136.56,24.28 136.22,23.95 R134.2 136.44,23.19 136.73,23.19 v1(136.93,23.39)
  L03_SIG1 w0.121: v1(111.87,25.84) 112.39,25.84 115.51,22.71 133.51,22.71 133.76,22.96 136.5,22.96 v1(136.93,23.39)
  BOTTOM w0.135: v1(136.93,23.39) 136.92,23.4 R134.2 ; U40.15 111.37,26.34 v1(111.87,25.84)
PRG1_CPSW_RGMII1_RXC: length 30.4
  TOP w0.135: R115.1 132.95,27.56 v1(132.28,27.56)
  L03_SIG1 w0.121: v1(110.68,25.84) 110.68,25.2 110.35,24.87 109.86,24.87 109.5,25.22 109.5,27.97 109.88,28.35 113.61,28.35 115.13,26.83 131.55,26.83 v1(132.28,27.56)
  BOTTOM w0.135: U40.16 v1(110.68,25.84)
PRG1_CPSW_RGMII1_RXC_R: length 2.8
  TOP w0.135: R115.2 134.5,27.57 135.21,28.28 U19.32
PRG1_CPSW_RGMII1_TD0: length 31.3
  TOP w0.135: U19.28 135.25,30.28 133.2,32.33 v1(132.51,32.33)
  L03_SIG1 w0.121: v1(132.51,32.33) 132.51,31.7 132.01,31.2 131.34,31.2 130.41,32.12 128.83,32.12 128.71,32 128.71,31.74 128.59,31.62 128.35,31.62 128.23,31.74 128.23,32 128.11,32.12 127.87,32.12 127.75,32 127.75,31.74 127.63,31.62 127.39,31.62 127.27,31.74 127.27,32 127.15,32.12 126.9,32.12 126.78,32 126.78,31.74 126.66,31.62 126.42,31.62 126.3,31.74 126.3,32 126.18,32.12 112.6,32.12 112.31,32.41 v1(111.87,32.41)
  BOTTOM w0.135: U40.2 111.44,32.84 v1(111.87,32.41)
PRG1_CPSW_RGMII1_TD1: length 31.2
  TOP w0.135: v1(134.16,32.94) 134.16,31.88 135.26,30.78 U19.27
  L03_SIG1 w0.121: v1(110.77,32.33) 111.28,31.83 113.26,31.83 113.86,31.22 125.47,31.22 125.75,30.94 132.29,30.94 133.53,32.18 134.44,32.18 134.86,32.6 134.86,32.78 134.7,32.94 v1(134.16,32.94)
  BOTTOM w0.135: v1(110.77,32.33) 110.77,32.34 U40.3
PRG1_CPSW_RGMII1_TD2: length 31.2
  TOP w0.135: U19.26 135.44,31.28 v1(134.92,31.8)
  L03_SIG1 w0.121: v1(134.92,31.8) 133.55,31.8 132.08,30.33 128.71,30.33 128.59,30.21 128.59,29.86 128.47,29.74 128.23,29.74 128.11,29.86 128.11,30.29 127.99,30.41 127.75,30.41 127.63,30.29 127.63,29.86 127.51,29.74 127.26,29.74 127.14,29.86 127.14,30.29 127.02,30.41 126.78,30.41 126.66,30.29 126.66,29.86 126.54,29.74 126.3,29.74 126.18,29.86 126.18,30.21 126.06,30.33 120.75,30.33 120.23,30.85 113.7,30.85 113.16,31.39 v1(111.87,31.39)
  BOTTOM w0.135: U40.4 111.42,31.84 v1(111.87,31.39)
PRG1_CPSW_RGMII1_TD3: length 31.2
  TOP w0.135: U19.25 135.88,31.78 135.69,31.98 v1(135.69,32.94)
  L03_SIG1 w0.121: v1(135.69,32.94) 136,32.63 136,31.71 135.33,31.04 133.4,31.04 131.84,29.48 120.59,29.48 120.3,29.76 113.57,29.76 112.37,30.96 111.05,30.96 v1(110.68,31.34)
  BOTTOM w0.135: U40.5 v1(110.68,31.34)
PRG1_CPSW_RGMII1_TX_CTL: length 31.3
  TOP w0.135: U19.37 137.18,24.79 137.19,24.79 v1(137.19,24.73)
  L03_SIG1 w0.121: v1(137.19,24.73) 133.8,28.12 115.32,28.12 114.71,28.73 112.85,28.73 111.87,29.71 v1(111.87,30.47)
  BOTTOM w0.135: v1(111.87,30.47) 111.5,30.84 U40.6
PRG1_CPSW_RGMII1_TXC: length 31.3
  TOP w0.135: v1(131.76,31.62) 133.35,31.62 135.19,29.78 U19.29
  L03_SIG1 w0.121: v1(131.76,31.62) 130.61,32.77 128.27,32.77 127.71,33.32 121.54,33.32 121.05,32.84 110.57,32.84 110.24,32.5 110.24,30.78 v1(110.68,30.34)
  BOTTOM w0.135: U40.7 v1(110.68,30.34)
PRG1_CPSW_RGMII2_CLK: length 19.5
  TOP w0.135: R13.1 138.79,55.32 138.28,55.83 133.35,55.83 132.18,54.66 132.18,48.34 130.58,46.74 R50.2
PRG1_CPSW_RGMII2_CLK_R: length 2.7
  TOP w0.135: U6.5 125.79,47.54 126.03,47.29 126.03,46.99 126.29,46.74 R50.1
PRG1_CPSW_RGMII2_GPIO_1: length 43.9
  TOP w0.135: R12.2 137.71,53.51 v1(137.72,53.52) 138.18,53.05 U7.22
  L03_SIG1 w0.121: v1(162.18,53.26) 162.18,54.31 160.35,56.13 139.83,56.13 137.72,54.03 v1(137.72,53.52)
  BOTTOM w0.135: R12.2 137.71,53.51 v1(137.72,53.52) ; v1(162.18,53.26) 162.18,44.96 162.94,44.2 Q12.3
PRG1_CPSW_RGMII2_RD0: length 73.7
  TOP w0.102: 87.62,30.36 U18.AA10
  TOP w0.135: v1(133.99,45.9) 133.83,45.75 133.83,45.3 R64.1 134.52,45.16 134.7,45.34 134.7,46.02 135.5,46.83 U7.33 ; v1(104.78,35.18) 103.99,35.18 103.33,34.52 103.33,33.61 102.74,33.02 101.98,33.02 98.73,29.77 89,29.77 88.41,30.36 87.62,30.36
  L03_SIG1 w0.121: v1(133.99,45.9) 133.4,45.31 132.72,45.31 132.23,45.8 131.62,45.8 131.45,45.97 131.45,47.88 131.33,48 130.99,48 130.87,47.88 130.87,45.68 130.74,45.56 130.44,45.56 130.28,45.72 130.28,47.73 130.13,47.88 129.79,47.88 127.93,46.02 120.86,46.02 117.26,42.43 117.26,42.14 116.87,41.74 116.58,41.74 115.4,40.56 115.4,40.56 114.63,39.79 114.63,37.74 113.27,36.37 102.74,36.37 102.62,36.25 102.62,35.3 102.74,35.18 v1(104.78,35.18)
  BOTTOM w0.135: v1(133.99,45.9) 133.99,45.2 R64.1
PRG1_CPSW_RGMII2_RD1: length 73.6
  TOP w0.102: 87.74,30.08 86.67,30.08 U18.Y10
  TOP w0.135: U7.34 135.64,46.33 135,45.69 135,44.23 134.51,43.74 R68.2 133.78,43.93 133.78,44.22 133.99,44.42 v1(133.99,44.44) ; v1(103.76,34.16) 103.76,33.66 102.82,32.72 102.18,32.72 98.96,29.49 88.87,29.49 88.28,30.08 87.74,30.08
  L03_SIG1 w0.121: v1(103.76,34.16) 103.23,33.63 102.36,33.63 102.23,33.51 102.23,33.01 102.36,32.89 104.14,32.89 107.11,35.86 113.48,35.86 116.53,38.91 118.44,38.91 119.38,39.86 119.38,41.27 122.4,44.29 123.6,44.29 123.72,44.41 123.72,45.39 123.84,45.51 124.08,45.51 124.2,45.39 124.2,43.7 124.32,43.58 124.57,43.58 124.69,43.7 124.69,45.39 124.81,45.51 125.05,45.51 125.17,45.39 125.17,44.41 125.29,44.29 125.53,44.29 125.65,44.41 125.65,45.39 125.77,45.51 126.01,45.51 126.13,45.39 126.13,44.41 126.45,44.09 127.1,44.09 127.44,44.44 v1(133.99,44.44)
  BOTTOM w0.135: R68.2 133.99,43.75 v1(133.99,44.44)
PRG1_CPSW_RGMII2_RD2: length 73.7
  TOP w0.102: 87.33,31.14 86.67,31.14 U18.Y11
  TOP w0.135: v1(132.49,42.6) 132.63,42.45 R71.1 133.24,42.45 133.82,43.03 134.29,43.03 135.28,44.02 135.28,45.52 135.6,45.83 U7.35 ; v1(100.63,32.56) 100.04,33.16 97.93,33.16 95.86,31.09 87.37,31.09 87.33,31.14
  L03_SIG1 w0.121: v1(132.49,42.6) 131.32,42.6 131.09,42.82 131.09,44.02 130.97,44.15 130.73,44.15 130.61,44.02 130.61,42.54 130.49,42.42 130.25,42.42 130.13,42.54 130.13,44.02 130.01,44.15 129.77,44.15 129.65,44.02 129.65,42.54 129.53,42.42 129.28,42.42 129.16,42.54 129.16,44.02 129.04,44.15 128.8,44.15 128.68,44.02 128.68,42.54 128.56,42.42 128.32,42.42 128.2,42.54 128.2,44.02 128.08,44.15 127.84,44.15 127.72,44.02 127.72,42.56 127.6,42.44 124.59,42.44 123.91,43.13 121.6,43.13 119.63,41.17 119.63,39.75 118.54,38.66 116.64,38.66 113.59,35.61 107.24,35.61 104.52,32.89 104.52,31.88 104.27,31.62 101.57,31.62 v1(100.63,32.56)
  BOTTOM w0.135: v1(132.49,42.6) 132.71,42.37 R230.2
PRG1_CPSW_RGMII2_RD3: length 73.6
  TOP w0.102: v2(85.36,30.9) 85.39,30.94 U18.V12
  TOP w0.135: U7.36 135.74,45.33 135.59,45.17 135.59,43.86 134.73,43 R72.1 134.94,42.24 135.28,42.24 v1(135.48,42.44)
  L03_SIG1 w0.102: 87.6,31.08 86.31,31.08 86.19,30.96 85.42,30.96 v2(85.36,30.9)
  L03_SIG1 w0.121: v1(135.48,42.44) 135.01,41.97 134.76,41.97 134.64,42.09 134.64,43.34 134.52,43.46 134.28,43.46 134.15,43.34 134.15,42.26 134.03,42.14 133.79,42.14 133.67,42.26 133.67,43.31 133.53,43.46 133.31,43.46 133.19,43.34 133.19,42.09 133.06,41.96 129.97,41.96 129.85,41.84 129.85,41.5 129.73,41.38 129.49,41.38 129.37,41.5 129.37,41.84 129.25,41.96 129.01,41.96 128.88,41.84 128.88,41.5 128.76,41.38 128.52,41.38 128.4,41.5 128.4,41.84 128.28,41.96 128.04,41.96 127.92,41.84 127.92,41.5 127.8,41.38 127.56,41.38 127.44,41.5 127.44,41.84 127.32,41.96 127.07,41.96 126.95,41.84 126.95,41.5 126.83,41.38 126.59,41.38 126.47,41.5 126.47,41.84 126.35,41.96 122.78,41.96 119.99,39.17 119.48,39.17 118.59,38.28 118.59,35.57 117.87,34.84 108.97,34.84 106.25,32.12 106.25,31.06 105.52,30.34 102.58,30.34 101.8,29.57 100.28,29.57 98.15,31.7 88.22,31.7 87.6,31.08
  BOTTOM w0.135: v1(135.48,42.44) 134.79,42.44 R229.2
PRG1_CPSW_RGMII2_RSTN: length 5.1
  TOP w0.135: U7.43 140.18,42.52 v1(139.06,41.4)
  BOTTOM w0.135: v1(139.06,41.4) 138.57,41.4 138.45,41.28 U34.4
PRG1_CPSW_RGMII2_RX_CTL: length 73.8
  TOP w0.102: 87.49,31.36 U18.Y12
  TOP w0.135: v1(136.93,42.44) 136.73,42.24 136.44,42.24 R73.2 136.22,42.99 136.56,43.33 137.41,43.33 137.68,43.6 U7.38 ; 87.49,31.36 95.62,31.36 97.69,33.43 99.97,33.43 v1(100.2,33.66)
  L03_SIG1 w0.121: v1(100.2,33.66) 101.22,34.67 105.33,34.67 106.78,36.12 113.38,36.12 116.5,39.24 118.4,39.24 118.6,39.44 118.6,41.51 119.27,42.18 119.73,42.18 119.9,42.35 119.9,42.52 119.08,43.34 119.08,43.51 119.25,43.68 119.42,43.68 120.24,42.86 120.43,42.86 120.59,43.02 120.59,43.19 119.76,44.02 119.76,44.19 119.93,44.36 120.1,44.36 120.94,43.52 121.14,43.52 121.3,43.68 121.3,43.85 120.44,44.71 120.44,44.88 120.61,45.05 120.78,45.05 121.63,44.2 121.85,44.2 121.99,44.35 121.99,44.52 121.12,45.39 121.12,45.56 121.33,45.76 126.7,45.76 127.7,44.76 132.9,44.76 133.17,45.03 134.34,45.03 v1(136.93,42.44)
  BOTTOM w0.135: R228.1 136.86,42.37 v1(136.93,42.44)
PRG1_CPSW_RGMII2_RXC: length 70.4
  TOP w0.102: U18.V10 84.98,30.36 v2(84.93,30.3)
  TOP w0.135: v1(132.18,46.61) 132.95,46.61 R51.1
  L03_SIG1 w0.121: v1(132.18,46.61) 134.19,46.61 136.35,44.45 136.35,43.79 137.54,42.6 137.54,41.36 136.34,40.17 131.79,40.17 131.29,40.67 125.29,40.67 123.74,39.12 121.92,39.12 120.98,38.18 120.98,36.55 118.76,34.33 110.93,34.33 104.56,27.97 103.48,27.97 102.85,28.6 96.8,28.6 95.63,29.77 87.6,29.77 87.35,30.02 85.21,30.02 v2(84.93,30.3)
PRG1_CPSW_RGMII2_RXC_R: length 2.8
  TOP w0.135: U7.32 135.21,47.33 134.5,46.62 R51.2
PRG1_CPSW_RGMII2_TD0: length 74.7
  TOP w0.102: 87.74,28.01 87.39,28.36 U18.Y6
  TOP w0.135: v1(112.52,37.34) 113,37.34 113.79,36.55 113.79,35.77 113.66,35.64 113.16,35.64 113.03,35.5 113.03,35.23 113.16,35.1 114.11,35.1 114.25,34.96 114.25,34.69 114.11,34.56 113.16,34.56 113.03,34.42 113.03,34.16 113.16,34.02 114.11,34.02 114.25,33.89 114.25,29.9 113.06,28.7 110.29,28.7 109.52,27.94 109.52,27.25 108.98,26.71 96.89,26.71 96.24,26.06 89.69,26.06 87.74,28.01 ; U7.28 135.06,49.33 134.66,49.73 v1(134.66,50.17)
  L03_SIG1 w0.121: v1(112.52,37.34) 112.52,38.88 115.46,41.82 115.46,42.43 116.79,43.76 122.21,49.17 122.21,49.56 122.97,50.32 130.08,50.32 130.6,50.84 133.99,50.84 v1(134.66,50.17)
PRG1_CPSW_RGMII2_TD1: length 74.8
  TOP w0.102: 87.74,29.15 87.73,29.16 87.09,29.16 U18.AA8
  TOP w0.135: v1(135.52,49.83) 135.56,49.83 135.56,49.83 U7.27 ; v1(111.3,37.34) 107.11,33.15 105.08,33.15 104.78,32.84 104.78,31.98 102.84,30.04 102.3,30.04 100.74,28.47 96.9,28.47 96.16,27.74 89.15,27.74 87.74,29.15
  L03_SIG1 w0.121: v1(135.52,49.83) 136.42,49.83 136.63,49.63 136.63,49.26 136.51,49.14 134.53,49.14 134.41,49.02 134.41,48.77 134.53,48.65 134.88,48.65 135,48.53 135,48.15 135.12,48.03 135.36,48.03 135.49,48.15 135.49,48.53 135.61,48.65 136.51,48.65 136.63,48.53 136.63,47.36 136.48,47.22 133.63,47.22 133.27,47.58 133.27,50.17 132.85,50.59 130.98,50.59 130.43,50.04 124.41,50.04 122.89,48.51 121.91,48.51 115.72,42.32 115.72,41.72 113.94,39.94 113.94,37.9 112.93,36.89 111.76,36.89 v1(111.3,37.34)
PRG1_CPSW_RGMII2_TD2: length 74.8
  TOP w0.102: U18.Y9 87.31,29.86
  TOP w0.135: v1(108.25,37.34) 105.59,34.67 105.28,34.67 103.12,32.51 103.12,32 102.49,31.37 101.22,31.37 99.08,29.23 88.66,29.23 88.14,29.74 87.43,29.74 87.31,29.86 ; v1(134.6,51.5) 134.6,51.05 135.32,50.33 U7.26
  L03_SIG1 w0.121: v1(108.25,37.34) 107.81,37.34 107.77,37.38 101.74,37.38 101.52,37.59 101.52,37.93 101.73,38.14 111.42,38.14 115.21,41.93 115.21,42.53 116.54,43.86 121.95,49.28 121.95,49.69 122.84,50.58 129.83,50.58 130.43,51.19 134.29,51.19 v1(134.6,51.5)
PRG1_CPSW_RGMII2_TD3: length 74.9
  TOP w0.102: v2(85.93,29.39) 85.89,29.44 U18.W9
  TOP w0.135: U7.25 135.74,50.83 135.52,51.06 v1(135.52,51.5)
  L03_SIG1 w0.121: v2(85.93,29.39) 87.04,29.39 87.17,29.26 95.05,29.26 96.22,28.09 102.62,28.09 103.3,27.41 106.54,27.41 109.65,30.52 109.65,32.28 110.46,33.09 112.96,33.09 113.4,33.53 120.37,33.53 123.67,36.83 123.67,38.33 125.5,40.15 130.56,40.15 131.06,39.66 136.56,39.66 138.84,41.94 138.84,45.92 137.29,47.47 137.29,49.73 v1(135.52,51.5)
PRG1_CPSW_RGMII2_TX_CTL: length 74.8
  TOP w0.102: U18.V9 85.39,29.44 v2(85.36,29.39)
  TOP w0.135: v1(137.19,43.78) 137.19,43.84 137.18,43.84 U7.37
  L03_SIG1 w0.121: v1(137.19,43.78) 137.19,44.22 135.01,46.4 135.01,46.67 135.25,46.91 137.48,46.91 138.58,45.82 138.58,42.04 136.45,39.91 131.16,39.91 130.66,40.41 125.39,40.41 123.72,38.73 123.1,38.73 122.28,37.91 122.28,36.71 119.47,33.91 113.42,33.91 112.86,33.35 110.36,33.35 109.4,32.39 109.4,31.46 105.65,27.71 103.37,27.71 102.74,28.34 96.47,28.34 95.3,29.52 87.43,29.52 87.18,29.76 85.73,29.76 v2(85.36,29.39)
PRG1_CPSW_RGMII2_TXC: length 8
  TOP w0.102: 87.74,29.44 87.35,29.44 87.15,29.64 86.67,29.64 U18.Y8
  TOP w0.135: 87.74,29.44 88.01,29.44 88.59,28.86 93.25,28.86 93.72,28.38 R23.1
PRG1_CPSW_RGMII2_TXC_R: length 67.1
  TOP w0.135: v1(109.78,37.34) 106.07,33.63 105.13,33.63 104.47,32.97 104.47,32.18 103.15,30.86 101.6,30.86 99.62,28.88 96.62,28.88 96.09,28.35 R23.2 ; U7.29 135.14,48.83 134.09,49.89 v1(132.61,49.89)
  L03_SIG1 w0.121: v1(132.61,49.89) 131.06,49.89 127.56,46.38 127.15,46.38 126.96,46.58 126.96,48.16 126.84,48.29 126.57,48.29 126.45,48.16 126.45,46.58 126.33,46.46 126.11,46.46 125.97,46.6 125.97,48.16 125.85,48.29 125.6,48.29 125.48,48.16 125.48,46.58 125.36,46.46 125.15,46.46 125,46.6 125,48.16 124.88,48.29 124.64,48.29 124.52,48.16 124.52,46.58 124.4,46.46 124.18,46.46 124.06,46.58 124.06,48.14 123.92,48.29 123.73,48.29 123.58,48.14 123.58,46.58 123.46,46.46 120.88,46.46 117.01,42.59 117.01,42.24 116.76,41.99 116.36,41.99 114.27,39.91 114.27,37.82 113.08,36.63 110.49,36.63 v1(109.78,37.34)
PRG1_CPSW_RGMII_INTN: length 93.5
  TOP w0.102: U18.AA13 87.03,32 87.74,32
  TOP w0.135: v1(124.44,35.94) 123.12,37.26 115.7,37.26 114.62,38.34 108.79,38.34 108.57,38.12 107.97,38.12 107.95,38.1 105.75,35.9 103.69,35.9 102.67,34.88 102.67,33.98 102.41,33.73 101.98,33.73 101.36,34.35 99.63,34.35 99.33,34.05 97.04,34.05 95,32 94.94,32 94.94,32 87.74,32 ; U19.44 140.68,24.85 141.66,23.88 R136.2 141.85,23.22 142.21,23.22 v1(142.39,23.39) ; v1(140.69,43) 140.68,43.01 U7.44
  L03_SIG1 w0.121: v1(124.44,35.94) 124.1,36.28 124.1,38.38 125.62,39.9 130.26,39.9 130.86,39.29 137.64,39.29 140.69,42.34 v1(140.69,43)
  BOTTOM w0.135: v1(142.39,23.39) 136.69,29.1 136.69,38.49 137.85,39.65 138.87,39.65 139.5,40.28 139.5,41.35 140.69,42.55 v1(140.69,43)
